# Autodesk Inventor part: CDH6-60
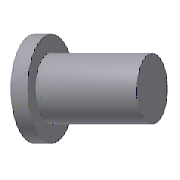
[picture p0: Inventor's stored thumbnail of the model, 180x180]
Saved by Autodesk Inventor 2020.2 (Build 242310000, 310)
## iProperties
Manager: www.cadconsulting.pl
Company: Fabian Stasiak CAD Consulting
Created: 2014-02
Part Number: CDH6-60
Material: SKD61
Description: Straight Core Pin
Document SubType Name: Modeling
Designer: F.Stasiak
Standard Revision: 1
Manufacturer: PUNCH
Language: pl-PL
Size Designation: 6-60
Categories: <MemberInstance><Categories><Category DisplayName="Forma wtryskowa" InternalName="349578f2-f4d4-4954-8c09-8e99297a61c0" Mnemonic="MOLD"><Category DisplayName="W
Mass: 1.61494 g
Surface Area: 11.4822 cm^2
Volume: 1.61494 cm^3
Density: 7.8 g/cm^3
Appearance: Aluminium - ciemne
Catalog Web Link: www.expertbooks.pl
IsCustomPart: 1
Author: F.Stasiak
Subject: Zbiór ćwiczeń. Autodesk Inventor 2020. Kurs Professional
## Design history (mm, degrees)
sketch "Sketch1"
  geometry: L1 (4.5, 0)-(4.5, 4); L2 (4.5, 4)-(3, 4); L3 (3, 4)-(3, 60); L4 (3, 60)-(0, 60); L5 (4.5, 0)-(0, 0); L6 (0, 0)-(0, 60); L7 (0, 60)-(0, -10) reference; 1 further point
  constraints: 14 end point, 2 horizontal, 1 coincident, 1 collinear, 1 parallel
  dimensions: "d2" = 4 distance of L1.start L1.end (= T_); "d19" = 60 distance between parallel lines of L4 L5 (= L); "d38" = 6 diameter of L3 L7 (= P); "d39" = 9 diameter of L1 L7 (= H_)
revolve "Revolution1" sketch "Sketch1" stored, may be unused: angle "d4" = 90 deg
fillet "Fillet1" dims "d36" = 0.3
workplane "Work Plane1"
sketch "Sketch2"
  geometry: 2 further points
  constraints: 1 vertical alignment
  dimensions: "d21" = 2 distance of point (0, -2) point (0, 0) (= 0.5 x T_)
hole "Anti_Rotary Hole" sketch "Sketch2" at (0, 0) diameter "d22" = 0.8 (= Anti_Rotary_D); stored, may be unused: countersink angle "d26" = 90 deg, drill point angle "d28" = 118 deg; dims "d23" = 6, "d24" = 4, "d25" = 2, "d27" = 1.2 (= 1.5 x Anti_Rotary_D)
sketch "Sketch3"
  geometry: L1 (-3.3, 3.059)-(-3.3, -3.059); A1 r 4.5 centre (0, 0) between (-3.3, 3.059) and (-3.3, -3.059) reference; 1 further point
  constraints: 2 end point, 2 point on circle, 1 vertical
  dimensions: "d29" = 3.3 distance from line of point (0, 0) L1 (= Anti_Rotary_P)
extrude "Anti_Rotary Plane" cut sketch "Sketch3" extent not by distance; stored distance "d30" = 10; taper "d31" = 0 deg
body "Solid1"
other parameters: "H_" = 9 [user parameter; used in 1 equation term], "L" = 60 [user parameter; used in 1 equation term], "P" = 6 [user parameter; used in 1 equation term], "d7" = 0, "d8" = 0, "T_" = 4 [user parameter; used in 2 equation terms], "Anti_Rotary_P" = 3.3 [user parameter; used in 1 equation term], "Anti_Rotary_D" = 0.8 [user parameter; used in 2 equation terms], "d32" = 0, "d33" = 0, "d34" = 0, "d35" = 0, "IsARPlane" = 0 [user parameter], "IsARHole" = 0 [user parameter]
